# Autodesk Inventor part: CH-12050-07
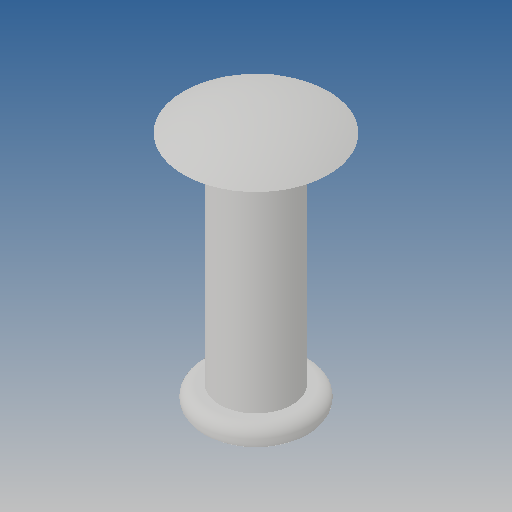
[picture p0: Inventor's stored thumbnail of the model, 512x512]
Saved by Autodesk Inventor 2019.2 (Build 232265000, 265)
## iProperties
Created: 2012-07
Part Number: CH-12050-07
Material: Ogólny
Document SubType Name: Modeling
Designer: CADENGINEERING4
Density: 1 g/cm^3
Appearance: Domyślna
Author: CADENGINEERING4
Revision Number: ÈÎºÎ
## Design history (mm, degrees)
feature "Ô²½Ç2"
node "Bryła1"
